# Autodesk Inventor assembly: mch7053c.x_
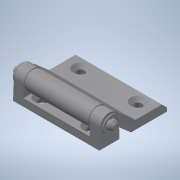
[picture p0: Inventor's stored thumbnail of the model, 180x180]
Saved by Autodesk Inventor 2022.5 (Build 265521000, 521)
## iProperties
Part Number: mch7053c.x_
Material: 一般
Document SubType Name: Assembly
Designer: ImaoCorp
Sending System: SOLIDWORKS 2017-2017317
MC: AMD64
MC_MODEL: Intel64 Family 6 Model 60 Stepping 3, GenuineIntel
OS: Windows_NT
FRU: Parasolid Version 29.0, build 201,  4-17-2017
FORMAT: text
GUISE: transmit
KEY: mch7053c
FILE: mch7053c.x_t
DATE: Fri Jul 26 11:41:47 2019
Author: ImaoCorp
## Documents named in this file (4)
- X:\14_SW2022-Inv2022\00_全2023-1023新製品(TCC)まで\m\mch7053c\MCH7053C.iam
- X:\14_SW2022-Inv2022\00_全2023-1023新製品(TCC)まで\m\mch7053c\mch7053c_01.ipt
- X:\14_SW2022-Inv2022\00_全2023-1023新製品(TCC)まで\m\mch7053c\mch7053c_02.ipt
- X:\14_SW2022-Inv2022\00_全2023-1023新製品(TCC)まで\m\mch7053c\mch7053c_03.ipt
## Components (3 placed, 3 different names)
1. mch7053c_01
2. mch7053c_02
3. mch7053c_03
